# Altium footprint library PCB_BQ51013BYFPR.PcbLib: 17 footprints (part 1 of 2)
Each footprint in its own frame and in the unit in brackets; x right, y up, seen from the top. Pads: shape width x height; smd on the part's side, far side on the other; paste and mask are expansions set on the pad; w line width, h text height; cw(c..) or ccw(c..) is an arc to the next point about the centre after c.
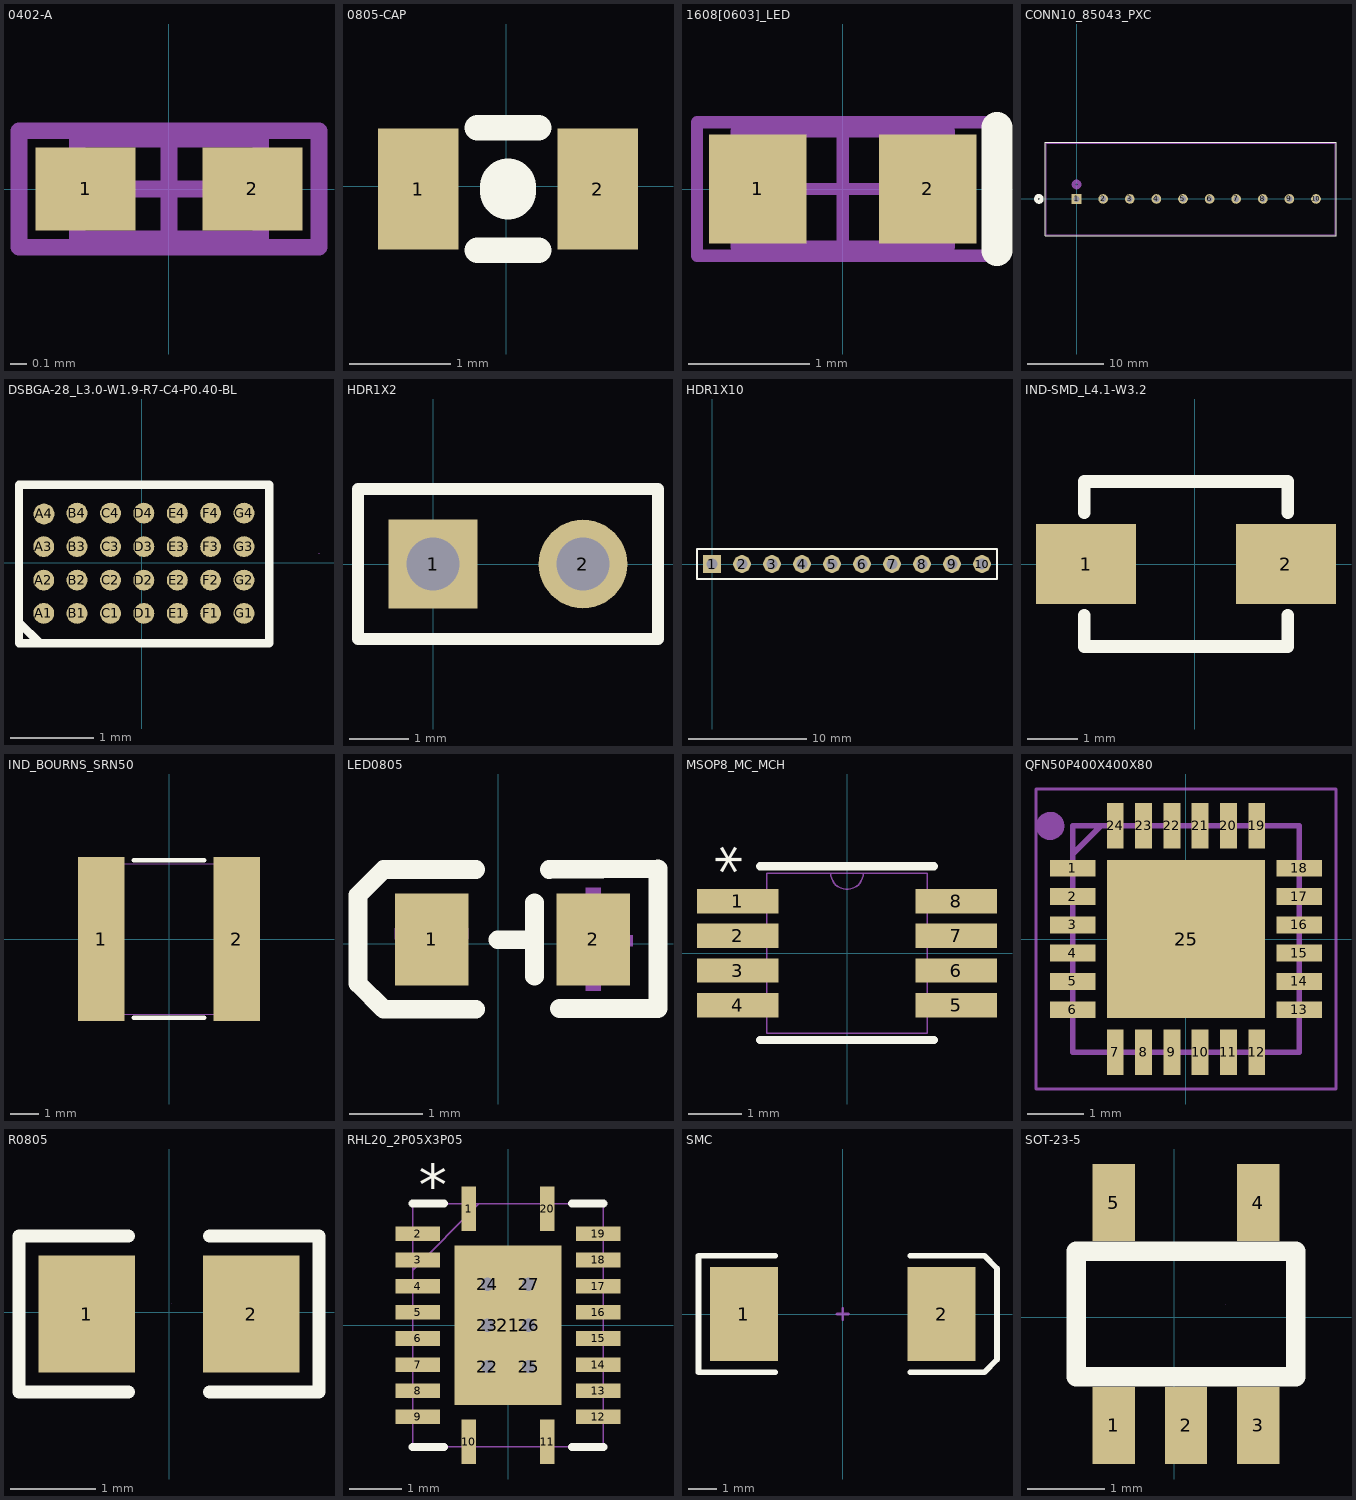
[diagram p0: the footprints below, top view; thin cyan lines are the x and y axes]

## 0402-A [mm] "Chip Inductor, Body 1.0x0.5mm, IPC High Density"
height 0.55
pads (2):
  rect 0.6x0.5 smd: 1(-0.5,0) 2(0.5,0)
Mechanical 13:
  lines w0.1: -0.55,-0.3 -0.55,0.3 0.55,0.3 0.55,-0.3 -0.55,-0.3
Mechanical 15:
  lines w0.1: -0.3,0 0.3,0 ; 0,-0.3 0,0.3 ; -0.9,-0.35 -0.9,0.35 0.9,0.35 0.9,-0.35 -0.9,-0.35
3D body: height 0.55, standoff 0, extent -0.55,-0.3 0.55,0.3

## 0805-CAP [mil]
height 104.33
pads (2):
  rect 31.5x47.2 smd: 1(-34.25,-1) 2(35.75,-1)
Top Overlay:
  lines w10: -11.25,-25 12.75,-25 ; -11.25,23 12.75,23
  lines w22: 0.75,-2 0.75,0
Mechanical 15:
  lines w0.1: 20.74,3.99 20.76,4.01

## 1608[0603]_LED [mm] "Chip Capacitor, Body 1.6x0.8mm, IPC High Density"
height 1.3
pads (2):
  rect 0.8x0.9 smd: 1(-0.7,0) 2(0.7,0)
Top Overlay:
  lines w0.254: 1.27,-0.508 1.27,0.508
Mechanical 13:
  lines w0.1: -0.875,-0.475 -0.875,0.475 0.875,0.475 0.875,-0.475 -0.875,-0.475
Mechanical 15:
  lines w0.1: -0.475,0 0.475,0 ; 0,-0.475 0,0.475 ; -1.2,-0.55 -1.2,0.55 1.2,0.55 1.2,-0.55 -1.2,-0.55
3D body: height 1.3, standoff 0, extent -0.875,-0.475 0.875,0.475

## CONN10_85043_PXC [mil]
pads (10):
  rect 50x50 hole 30 mask-1000: 1(0,0)
  round 50 hole 30 mask-1000: 2(137.8,0) 3(275.59,0) 4(413.39,0) 5(551.18,0) 6(688.98,0) 7(826.77,0) 8(964.57,0) 9(1102.36,0) 10(1240.16,0)
Top Overlay:
  circle w20: c-195,0 r15
  lines w6: -162.42,-189.6 1343.58,-189.6 1343.58,292.4 -162.42,292.4 -162.42,-189.6
Bottom Overlay:
  circle w20: c-195,0 r15
Top Solder:
  drawing of 10 lines, arcs and shapes, not listed
Bottom Solder:
  drawing of 10 lines, arcs and shapes, not listed
Mechanical 1:
  circle w20: c0,75 r15
  lines w1: -157.42,-184.6 1338.58,-184.6 1338.58,287.4 -157.42,287.4 -157.42,-184.6

## DSBGA-28_L3.0-W1.9-R7-C4-P0.40-BL [mm]
height 2.65
pads (28):
  round 0.25 smd: A1(-1.176,-0.607) A2(-1.176,-0.208) A3(-1.176,0.193) A4(-1.173,0.584) B1(-0.777,-0.607) B2(-0.777,-0.208) B3(-0.777,0.193) B4(-0.777,0.594) C1(-0.376,-0.607) C2(-0.376,-0.208) C3(-0.376,0.193) C4(-0.376,0.594) D1(0.023,-0.607) D2(0.023,-0.208) D3(0.023,0.193) D4(0.023,0.594) E1(0.424,-0.607) E2(0.424,-0.208) E3(0.424,0.193) E4(0.424,0.594) F1(0.823,-0.607) F2(0.823,-0.208) F3(0.823,0.193) F4(0.823,0.594) G1(1.224,-0.607) G2(1.224,-0.208) G3(1.224,0.193) G4(1.224,0.594)
Top Overlay:
  lines w0.1: -1.473,-0.965 -1.473,0.935 1.527,0.935 1.527,-0.965 -1.473,-0.965
  lines w0.102: -1.473,-0.715 -1.223,-0.965
Mechanical 15:
  lines w0.003: 2.122,0.111 2.122,0.112

## HDR1X2 [mm] "Connector; Header; 2 Position"
height 2.65
pads (2):
  rect 1.5x1.5 hole 0.9: 1(0,0)
  round 1.5 hole 0.9: 2(2.54,0)
Top Overlay:
  lines w0.2: -1.27,-1.27 -1.27,1.27 3.81,1.27 3.81,-1.27 -1.27,-1.27

## HDR1X10 [mm] "Connector; Header; 10 Position"
height 2.65
pads (10):
  rect 1.5x1.5 hole 0.9: 1(0,0)
  round 1.5 hole 0.9: 2(2.54,0) 3(5.08,0) 4(7.62,0) 5(10.16,0) 6(12.7,0) 7(15.24,0) 8(17.78,0) 9(20.32,0) 10(22.86,0)
Top Overlay:
  lines w0.2: -1.27,-1.27 24.13,-1.27 24.13,1.27 0.635,1.27 -1.27,1.27 -1.27,-1.27

## IND-SMD_L4.1-W3.2 [mm]
height 2.65
pads (2):
  rect 2x1.6 smd: 1(-2.175,0) 2(1.825,0)
Top Overlay:
  lines w0.254: -2.207,-1.031 -2.207,-1.651 1.857,-1.651 1.857,-1.031 ; -2.207,1.031 -2.207,1.651 1.857,1.651 1.857,1.031
Mechanical 15:
  lines w0.003: 0.904,0.127 0.905,0.127

## IND_BOURNS_SRN50 [mil]
pads (2):
  rect 63x224 smd: 1(-92.5,0) 2(92.5,0)
Top Overlay:
  lines w6: -47.9,-107.5 47.9,-107.5 ; -47.9,107.5 47.9,107.5
Mechanical 1:
  lines w1: -102.5,-102.5 102.5,-102.5 102.5,102.5 -102.5,102.5 -102.5,-102.5

## LED0805 [mm]
height 2.65
pads (2):
  rect 1x1.25 smd: 1(-0.905,0.061) 2(1.295,0.061)
Top Overlay:
  lines w0.254: -0.305,-0.889 -1.555,-0.889 ; -0.305,1.011 -1.555,1.011 ; -0.005,0.056 0.495,0.056 ; 0.495,-0.439 0.495,0.561 ; 0.695,1.011 2.175,1.021 2.175,-0.879 0.835,-0.879 ; -1.555,-0.889 -1.905,-0.539 -1.905,0.661 -1.555,1.011 ; -1.555,-0.889 -1.555,-0.889 ; -1.555,1.011 -1.555,1.011
Mechanical 15:
  region: -1.405,0.061 -0.405,0.061 -0.405,0.211 -1.405,0.211
  region: 0.83,-0.033 1.83,-0.033 1.83,0.117 0.83,0.117
  region: 1.195,0.761 1.395,0.761 1.395,-0.639 1.195,-0.639

## MSOP8_MC_MCH [mil]
pads (8):
  rect 60x18 smd: 1(-80.5,38.39) 2(-80.5,12.8) 3(-80.5,-12.8) 4(-80.5,-38.39) 5(80.5,-38.39) 6(80.5,-12.8) 7(80.5,12.8) 8(80.5,38.39)
Top Overlay:
  lines w6: -64,-64 64,-64 ; -64,64 64,64
  text "*" at -64.61,58 h31.25
Mechanical 1:
  lines w1: -12,59 ccw(c0,59) 12,59 ; -96.5,-46.39 -96.5,-30.39 -59,-30.39 -59,-46.39 -96.5,-46.39 ; -96.5,-20.8 -96.5,-4.8 -59,-4.8 -59,-20.8 -96.5,-20.8 ; -96.5,4.8 -96.5,20.8 -59,20.8 -59,4.8 -96.5,4.8 ; -96.5,30.39 -96.5,46.39 -59,46.39 -59,30.39 -96.5,30.39 ; -59,-59 59,-59 59,59 -59,59 -59,-59 ; 59,-46.39 59,-30.39 96.5,-30.39 96.5,-46.39 59,-46.39 ; 59,-20.8 59,-4.8 96.5,-4.8 96.5,-20.8 59,-20.8 ; 59,4.8 59,20.8 96.5,20.8 96.5,4.8 59,4.8 ; 59,30.39 59,46.39 96.5,46.39 96.5,30.39 59,30.39
  text "*" at -64.61,58 h31.25

## QFN50P400X400X80 [mil]
height 104.33
pads (25):
  rect 31.5x11.81 smd: 1(-78.42,49.52) 2(-78.42,29.84) 3(-78.42,10.15) 4(-78.42,-9.53) 5(-78.42,-29.21) 6(-78.42,-48.9) 13(79.06,-48.9) 14(79.06,-29.21) 15(79.06,-9.53) 16(79.06,10.15) 17(79.06,29.84) 18(79.06,49.52)
  rect 11.81x31.5 smd: 7(-48.9,-78.42) 8(-29.21,-78.42) 9(-9.53,-78.42) 10(10.15,-78.42) 11(29.84,-78.42) 12(49.52,-78.42) 19(49.52,79.06) 20(29.84,79.06) 21(10.15,79.06) 22(-9.53,79.06) 23(-29.21,79.06) 24(-48.9,79.06)
  rect 110.24x110.24 smd: 25(0.32,0.32)
Mechanical 15:
  lines w1.97: -104.02,-104.02 -104.02,104.64 104.64,104.64 104.64,-104.02 -104.02,-104.02
  lines w3.94: -78.42,59.38 -58.74,79.06 ; -78.42,-78.42 -78.42,79.06 79.06,79.06 79.06,-78.42 -78.42,-78.42
  lines w9.84: -89.26,78.84 cw(c-94.17,78.94) -89.26,79.05

## R0805 [mm]
height 2.65
pads (2):
  rect 1.133x1.377 smd: 1(-0.966,-0.023) 2(0.966,-0.023)
Top Overlay:
  lines w0.152: -0.476,-0.94 -1.761,-0.94 -1.761,0.894 -0.476,0.894 ; 0.476,-0.94 1.761,-0.94 1.761,0.894 0.476,0.894
Top Paste:
  region: -1.7,-0.663 -1.7,0.617 -1.65,0.667 -0.5,0.667 -0.45,0.617 -0.445,0.207 -0.895,0.207 -0.895,-0.243 -0.455,-0.243 -0.45,-0.663 -0.5,-0.713 -1.65,-0.713
  region: 0.45,-0.663 0.45,-0.243 0.895,-0.243 0.895,0.207 0.455,0.207 0.45,0.617 0.5,0.667 1.65,0.667 1.7,0.617 1.7,-0.663 1.65,-0.713 0.5,-0.713
Mechanical 15:
  lines w0.003: 0.029,0.104 0.03,0.105

## RHL20_2P05X3P05 [mm]
height 1.4
pads (27):
  rect 0.28x0.85 smd: 1(-0.75,2.225) 10(-0.75,-2.225) 11(0.75,-2.225) 20(0.75,2.225)
  rect 0.85x0.28 smd: 2(-1.725,1.75) 3(-1.725,1.25) 4(-1.725,0.75) 5(-1.725,0.25) 6(-1.725,-0.25) 7(-1.725,-0.75) 8(-1.725,-1.25) 9(-1.725,-1.75) 12(1.725,-1.75) 13(1.725,-1.25) 14(1.725,-0.75) 15(1.725,-0.25) 16(1.725,0.25) 17(1.725,0.75) 18(1.725,1.25) 19(1.725,1.75)
  rect 2.05x3.05 smd: 21(0,0)
  round 0.508 hole 0.254 mask-25.4: 22(-0.394,-0.787) 23(-0.394,0) 24(-0.394,0.787) 25(0.394,-0.787) 26(0.394,0) 27(0.394,0.787)
Top Overlay:
  lines w0.152: -1.825,-2.325 -1.223,-2.325 ; -1.825,2.325 -1.223,2.325 ; 1.223,-2.325 1.825,-2.325 ; 1.223,2.325 1.825,2.325
  text "*" at -1.707,2.29 h0.79
Top Solder:
  region: 0.394,1.046 0.295,1.027 0.211,0.971 0.154,0.887 0.135,0.787 0.154,0.688 0.211,0.604 0.295,0.548 0.394,0.528 0.493,0.548 0.577,0.604 0.633,0.688 0.653,0.787 0.633,0.887 0.577,0.971 0.493,1.027
  region: 0.394,0.259 0.295,0.239 0.211,0.183 0.154,0.099 0.135,0 0.154,-0.099 0.211,-0.183 0.295,-0.239 0.394,-0.259 0.493,-0.239 0.577,-0.183 0.633,-0.099 0.653,0 0.633,0.099 0.577,0.183 0.493,0.239
  region: 0.394,-0.528 0.295,-0.548 0.211,-0.604 0.154,-0.688 0.135,-0.787 0.154,-0.887 0.211,-0.971 0.295,-1.027 0.394,-1.046 0.493,-1.027 0.577,-0.971 0.633,-0.887 0.653,-0.787 0.633,-0.688 0.577,-0.604 0.493,-0.548
  region: -0.394,1.046 -0.493,1.027 -0.577,0.971 -0.633,0.887 -0.653,0.787 -0.633,0.688 -0.577,0.604 -0.493,0.548 -0.394,0.528 -0.295,0.548 -0.211,0.604 -0.154,0.688 -0.135,0.787 -0.154,0.887 -0.211,0.971 -0.295,1.027
  region: -0.394,0.259 -0.493,0.239 -0.577,0.183 -0.633,0.099 -0.653,0 -0.633,-0.099 -0.577,-0.183 -0.493,-0.239 -0.394,-0.259 -0.295,-0.239 -0.211,-0.183 -0.154,-0.099 -0.135,0 -0.154,0.099 -0.211,0.183 -0.295,0.239
  region: -0.394,-0.528 -0.493,-0.548 -0.577,-0.604 -0.633,-0.688 -0.653,-0.787 -0.633,-0.887 -0.577,-0.971 -0.493,-1.027 -0.394,-1.046 -0.295,-1.027 -0.211,-0.971 -0.154,-0.887 -0.135,-0.787 -0.154,-0.688 -0.211,-0.604 -0.295,-0.548
Bottom Solder:
  region: 0.394,1.046 0.295,1.027 0.211,0.971 0.154,0.887 0.135,0.787 0.154,0.688 0.211,0.604 0.295,0.548 0.394,0.528 0.493,0.548 0.577,0.604 0.633,0.688 0.653,0.787 0.633,0.887 0.577,0.971 0.493,1.027
  region: 0.394,0.259 0.295,0.239 0.211,0.183 0.154,0.099 0.135,0 0.154,-0.099 0.211,-0.183 0.295,-0.239 0.394,-0.259 0.493,-0.239 0.577,-0.183 0.633,-0.099 0.653,0 0.633,0.099 0.577,0.183 0.493,0.239
  region: 0.394,-0.528 0.295,-0.548 0.211,-0.604 0.154,-0.688 0.135,-0.787 0.154,-0.887 0.211,-0.971 0.295,-1.027 0.394,-1.046 0.493,-1.027 0.577,-0.971 0.633,-0.887 0.653,-0.787 0.633,-0.688 0.577,-0.604 0.493,-0.548
  region: -0.394,1.046 -0.493,1.027 -0.577,0.971 -0.633,0.887 -0.653,0.787 -0.633,0.688 -0.577,0.604 -0.493,0.548 -0.394,0.528 -0.295,0.548 -0.211,0.604 -0.154,0.688 -0.135,0.787 -0.154,0.887 -0.211,0.971 -0.295,1.027
  region: -0.394,0.259 -0.493,0.239 -0.577,0.183 -0.633,0.099 -0.653,0 -0.633,-0.099 -0.577,-0.183 -0.493,-0.239 -0.394,-0.259 -0.295,-0.239 -0.211,-0.183 -0.154,-0.099 -0.135,0 -0.154,0.099 -0.211,0.183 -0.295,0.239
  region: -0.394,-0.528 -0.493,-0.548 -0.577,-0.604 -0.633,-0.688 -0.653,-0.787 -0.633,-0.887 -0.577,-0.971 -0.493,-1.027 -0.394,-1.046 -0.295,-1.027 -0.211,-0.971 -0.154,-0.887 -0.135,-0.787 -0.154,-0.688 -0.211,-0.604 -0.295,-0.548
Mechanical 1:
  lines w0.025: -1.825,1.055 -0.555,2.325 ; -1.825,-2.325 -1.825,2.325 1.825,2.325 1.825,-2.325 -1.825,-2.325
  text "*" at -1.702,2.276 h0.79

## SMC [mm] "DO-214-AB/SMC; 2 C-Bend Leads; Body 7.9 x 5.9 mm, inc. leads (LxW)"
height 2.65
pads (2):
  rect 2.4x3.3 smd: 1(-3.475,0) 2(3.475,0)
Top Overlay:
  lines w0.2: -2.375,-2.05 -5.075,-2.05 -5.075,2.05 -2.375,2.05 ; 2.375,-2.05 4.975,-2.05 5.425,-1.6 5.425,1.6 4.975,2.055 ; 2.375,2.05 4.975,2.05
Mechanical 1:
  lines w0.1: -0.2,0 0.2,0 ; 0,-0.2 0,0.2

## SOT-23-5 [mm]
height 2.65
pads (5):
  rect 0.551x1 smd: 1(-0.787,-1.405) 2(0.152,-1.405) 3(1.092,-1.405) 4(1.092,1.491) 5(-0.787,1.491)
Top Overlay:
  lines w0.254: -1.168,-0.77 -1.27,-0.77 ; -1.168,0.856 -1.27,0.856 ; -0.381,-0.77 -0.279,-0.77 ; -0.381,0.856 0.686,0.856 ; 0.584,-0.77 0.686,-0.77 ; 1.473,-0.77 1.575,-0.77 ; 1.473,0.856 1.575,0.856 ; -1.27,-0.77 1.575,-0.77 ; -1.27,-0.77 -1.27,0.856 ; -1.27,0.856 0.991,0.856 1.575,0.856 ; 1.575,-0.77 1.575,0.856
Mechanical 15:
  lines w0.003: 0.66,0.17 0.661,0.17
